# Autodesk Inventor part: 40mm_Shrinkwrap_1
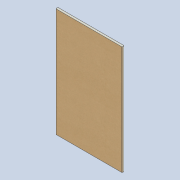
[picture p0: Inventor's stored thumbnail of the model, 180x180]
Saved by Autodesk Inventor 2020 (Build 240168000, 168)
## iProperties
Created: 2020-11
Part Number: 40mm_Shrinkwrap_1
Material: Generic
Document SubType Name: Modeling
Designer: Yolande
Density: 1 g/cm^3
Appearance: Default
description: 0:0:Lambdaboard 40mm Kraft
manufacturer: 0:0:Lambdaboard T/A Rigifoam
model: 0:0:
url: 0:0:www.lambdaboard.com
Author: Yolande
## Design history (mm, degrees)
derived "40mm.iam"
body "Solid1"
node "Lambdaboard 40mm Kraft.ipt:1" dims "d0" = 10
